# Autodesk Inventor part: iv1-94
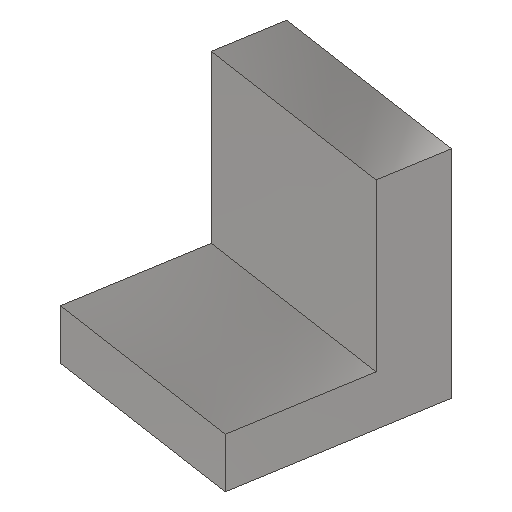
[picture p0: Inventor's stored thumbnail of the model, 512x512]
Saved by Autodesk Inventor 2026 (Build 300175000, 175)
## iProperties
Created: 2004-09
Part Number: iv1-94
Document SubType Name: Modeling
Designer: Lars Bertram Pedersen
Manufacturer: Standard
Standards Organization: Custom
Material: Steel, Mild
Density: 7.85 g/cm^3
Appearance: Semi-Polished
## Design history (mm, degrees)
sketch "Sketch1"
  geometry: L1 (-60, 0)-(0, 0); L2 (0, 0)-(0, 15); L3 (0, 15)-(-40, 15); L4 (-40, 15)-(-40, 65); L5 (-40, 65)-(-60, 65); L6 (-60, 65)-(-60, 0); 1 further point
  constraints: 12 end point, 3 perpendicular, 2 parallel, 1 coincident, 1 horizontal
  dimensions: "d0" = 60 distance of L1.start L1.end; "d1" = 15 distance of L1.end L2.end; "d2" = 50 distance of L3.end L4.end; "d3" = 20 distance of L4.end L5.end
extrude "Extrusion1" new body sketch "Sketch1" distance "d4" = 60; taper "d5" = 0 deg
body "Solid1"
